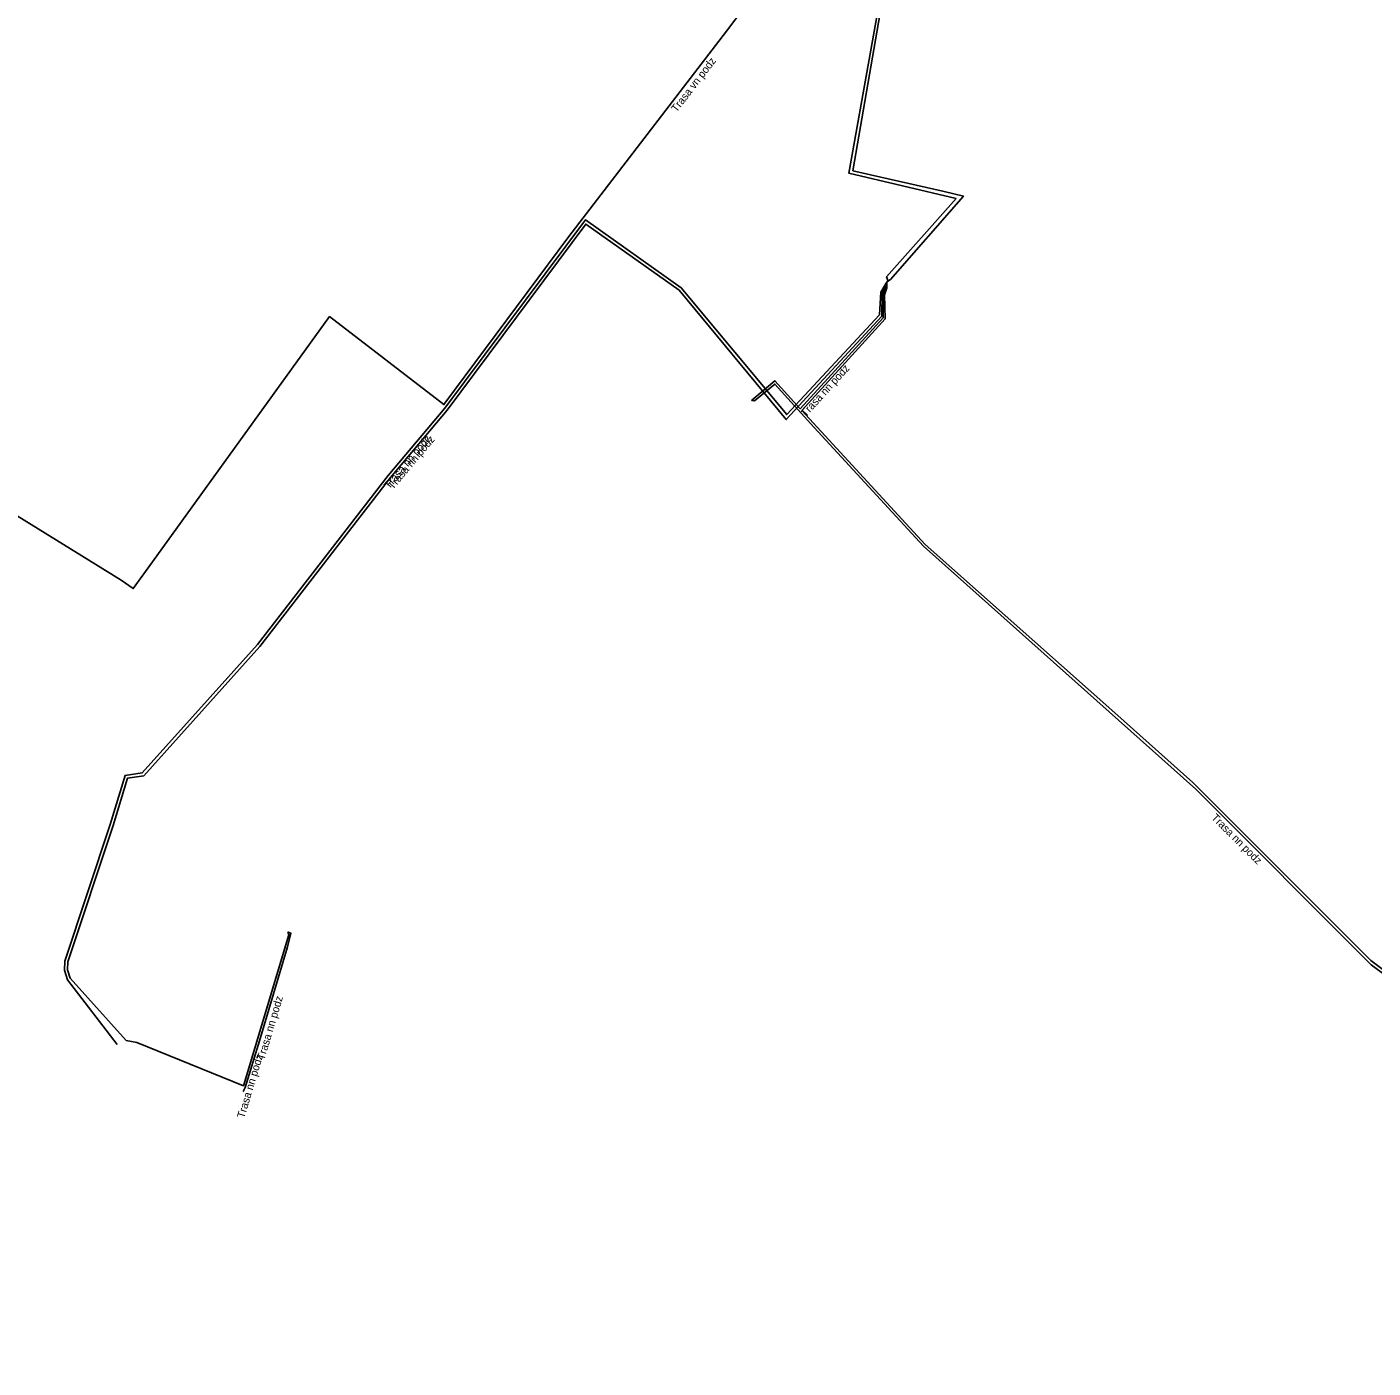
# Model space of a CAD drawing. Extents: x -875087 to -874407, y -1056142 to -1055396.
# Drawn here: x -874561.5 to -874474.3, y -1055976.3 to -1055889.5 of the extents above; entities that cross this region are included whole.
import ezdxf

# ---------------------------------------------------------------- set-up
doc = ezdxf.new("R2010")
doc.units = 0
for name, color, linetype in [('Popiskový text - Ostatní atributy Trasy', 7, 'Continuous'), ('Spojnice NN', 7, 'Continuous'), ('Spojnice VN', 7, 'Continuous')]:
    doc.layers.add(name, color=color, linetype=linetype)

msp = doc.modelspace()

# ---------------------------------------------------------------- linework, layer by layer
at = {"layer": 'Spojnice NN'}
for points in [[(-874476.442, -1055879.876), (-874476.736, -1055880.203), (-874477.848, -1055885.696), (-874489.98, -1055883.29), (-874492.735, -1055882.708), (-874496.092, -1055882.264), (-874506.31, -1055887.992), (-874508.27, -1055898.984), (-874501.334, -1055900.628), (-874505.836, -1055905.7), (-874505.726, -1055905.986), (-874505.826, -1055906.014)], [(-874476.442, -1055879.876), (-874476.636, -1055880.236), (-874477.731, -1055885.879), (-874488.718, -1055883.721), (-874492.752, -1055882.875), (-874496.092, -1055882.47), (-874506.156, -1055888.096), (-874508.013, -1055898.829), (-874502.114, -1055900.177), (-874500.856, -1055900.472), (-874505.589, -1055905.875), (-874505.826, -1055906.014)], [(-874505.826, -1055906.014), (-874505.855, -1055906.104), (-874506.212, -1055906.688), (-874506.294, -1055908.153), (-874512.29, -1055914.615), (-874519.131, -1055906.406), (-874525.329, -1055902.005), (-874534.428, -1055914.192), (-874538.111, -1055918.56), (-874546.556, -1055929.5), (-874554.022, -1055937.811), (-874555.139, -1055937.979), (-874556.105, -1055941.153), (-874559.032, -1055950.009), (-874559.064, -1055950.581), (-874558.87, -1055951.205), (-874555.656, -1055955.39)], [(-874505.826, -1055906.014), (-874505.942, -1055906.38), (-874506.112, -1055906.73), (-874506.15, -1055908.245), (-874512.33, -1055914.935), (-874519.258, -1055906.566), (-874525.304, -1055902.28), (-874534.289, -1055914.33), (-874537.952, -1055918.681), (-874546.402, -1055929.629), (-874553.922, -1055937.998), (-874554.984, -1055938.157), (-874555.914, -1055941.212), (-874558.834, -1055950.047), (-874558.862, -1055950.557), (-874558.692, -1055951.104), (-874555.068, -1055955.135)], [(-874505.826, -1055906.014), (-874505.884, -1055906.396), (-874506.048, -1055906.794), (-874506.054, -1055908.34), (-874511.427, -1055914.231), (-874513.064, -1055912.421), (-874514.56, -1055913.686), (-874514.571, -1055913.683)], [(-874505.826, -1055906.014), (-874505.822, -1055906.41), (-874505.971, -1055906.853), (-874505.92, -1055908.418), (-874511.311, -1055914.346), (-874503.334, -1055923.025), (-874491.05, -1055933.919), (-874486.009, -1055938.439), (-874474.478, -1055949.97), (-874466.276, -1055956.107), (-874455.879, -1055967.243), (-874452.496, -1055973.849), (-874450.885, -1055976.184), (-874432.104, -1055999.751), (-874421.292, -1056014.137), (-874421.161, -1056014.367), (-874421.241, -1056017.106), (-874423.047, -1056019.856), (-874426.896, -1056022.883), (-874439.852, -1056033.974), (-874444.03, -1056038.393), (-874446.391, -1056041.178), (-874449.872, -1056050.712)], [(-874514.571, -1055913.683), (-874514.56, -1055913.692), (-874514.379, -1055913.721), (-874513.064, -1055912.64), (-874510.525, -1055915.444), (-874503.445, -1055923.136), (-874485.81, -1055938.859), (-874474.455, -1055950.246), (-874466.588, -1055956.031), (-874456.085, -1055967.403), (-874452.578, -1055974.059), (-874453.306, -1055974.64), (-874453.582, -1055974.822)], [(-874555.068, -1055955.135), (-874554.38, -1055955.259), (-874547.46, -1055958.072), (-874544.534, -1055948.3), (-874544.591, -1055948.131), (-874544.598, -1055948.115)], [(-874547.49, -1055958.448), (-874547.48, -1055958.445), (-874547.364, -1055958.183), (-874546.422, -1055955.158), (-874544.612, -1055949.07), (-874544.394, -1055948.197), (-874544.584, -1055948.126), (-874544.598, -1055948.115)]]:
    msp.add_lwpolyline(points, dxfattribs=at)
at = {"layer": 'Spojnice VN'}
for points in [[(-874476.437, -1055879.881), (-874475.738, -1055876.979), (-874496.813, -1055869.192), (-874503.709, -1055873.287), (-874510.442, -1055881.994), (-874515.97, -1055889.516), (-874526.398, -1055903.078), (-874534.49, -1055913.963), (-874541.898, -1055908.264), (-874553.911, -1055924.923)], [(-874709.744, -1056039.584), (-874699.063, -1056016.976), (-874698.38, -1056016.928), (-874697.438, -1056016.952), (-874696.589, -1056016.387), (-874691.229, -1056006.251), (-874690.923, -1056005.579), (-874690.434, -1056004.234), (-874690.465, -1056003.348), (-874690.587, -1056002.859), (-874688.594, -1055994.675), (-874672.372, -1055964.102), (-874661.293, -1055948.443), (-874644.159, -1055934.263), (-874629.683, -1055925.991), (-874616.092, -1055921.854), (-874579.903, -1055910.185), (-874555.378, -1055925.335), (-874554.604, -1055925.879), (-874553.98, -1055925.018), (-874553.911, -1055924.923)]]:
    msp.add_lwpolyline(points, dxfattribs=at)

# ---------------------------------------------------------------- texts
at = {"layer": 'Popiskový text - Ostatní atributy Trasy'}
for s, rotation, p in [('Trasa vn podz', 52.44034, (-874519.428, -1055895.08)), ('Trasa nn podz', 47.63435, (-874511.071, -1055914.806)), ('Trasa nn podz', 49.86478, (-874538.032, -1055919.474)), ('Trasa nn podz', 49.90518, (-874537.797, -1055919.506)), ('Trasa nn podz', 314.91749, (-874484.84, -1055940.753)), ('Trasa nn podz', 73.44614, (-874546.125, -1055956.439)), ('Trasa nn podz', 73.33048, (-874547.42, -1055960.206))]:
    msp.add_text(s, height=0.5, rotation=rotation, dxfattribs=at).set_placement(p)

doc.saveas('drawing.dxf')
